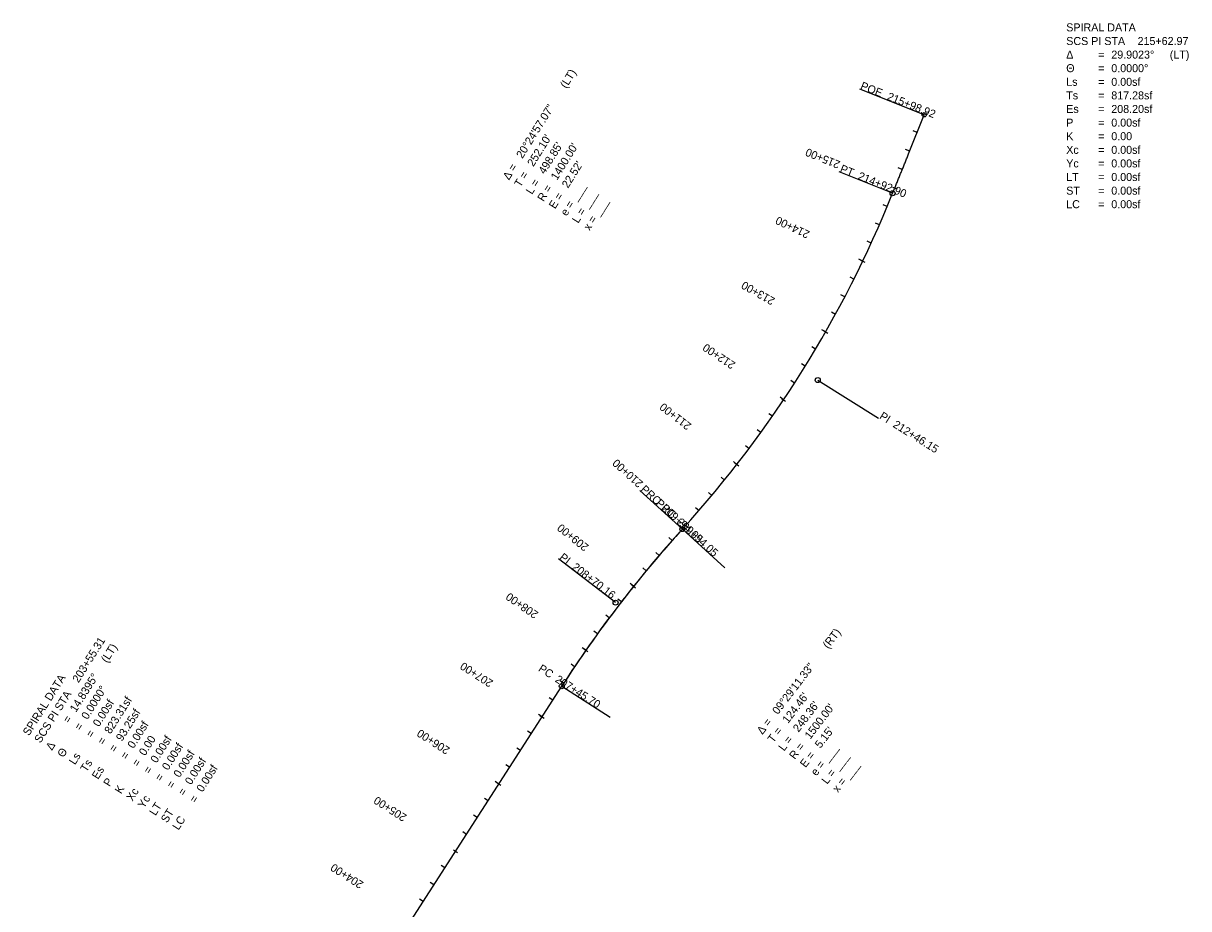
# Model space of a CAD drawing. Extents: x 14118619 to 14120230, y 8668091 to 8670317.
# Drawn here: x 14118771 to 14120230, y 8669208 to 8670317 of the extents above; entities that cross this region are included whole.
import ezdxf

# ---------------------------------------------------------------- set-up
doc = ezdxf.new("R2010")
doc.units = 0
for name, color, linetype in [('Default', 7, 'Continuous'), ('PhoBuilding', 7, 'Continuous'), ('PhoDrainageArrow', 7, 'Continuous'), ('PhoEdgeEntranceUnpaved', 7, 'Continuous'), ('PhoEdgeParkingUnpaved', 7, 'Continuous'), ('PhoGuardRail', 7, 'Continuous'), ('PhoRoadPoints', 7, 'Continuous')]:
    doc.layers.add(name, color=color, linetype=linetype)

msp = doc.modelspace()

# ---------------------------------------------------------------- linework, layer by layer
at = {"layer": 'Default'}
msp.add_open_spline([(14119859, 8670104.2), (14119859.4, 8670105), (14119860.1, 8670106.7), (14119861.1, 8670109.1), (14119862.1, 8670111.6), (14119863.1, 8670114), (14119864.1, 8670116.5), (14119865.1, 8670119), (14119866.1, 8670121.4), (14119867.1, 8670123.9), (14119868.1, 8670126.3), (14119869.1, 8670128.8), (14119870.1, 8670131.3), (14119871.1, 8670133.7), (14119872.1, 8670136.2), (14119873.1, 8670138.7), (14119874.1, 8670141.1), (14119875.1, 8670143.6), (14119876.1, 8670146.1), (14119877.1, 8670148.5), (14119878.1, 8670151), (14119878.7, 8670152.6), (14119879, 8670153.5)], degree=3, dxfattribs=at)
at = {"layer": 'PhoBuilding'}
for p, q in [((14119858.9, 8670111.9), (14119864.6, 8670109.6)), ((14119821.7, 8670019.2), (14119816.7, 8670021.5)), ((14119775.2, 8669930.6), (14119770.5, 8669933.3)), ((14119722.6, 8669845.6), (14119718.1, 8669848.7)), ((14119664, 8669764.6), (14119659.7, 8669768)), ((14119597.5, 8669690), (14119602.1, 8669685.9)), ((14119534.8, 8669612), (14119530.6, 8669615.4)), ((14119475, 8669531.9), (14119470.5, 8669535)), ((14119420.1, 8669448.3), (14119415.5, 8669451.3)), ((14119366, 8669364.2), (14119361.4, 8669367.2)), ((14119309.3, 8669281.8), (14119314.4, 8669278.5))]:
    msp.add_line(p, q, dxfattribs=at)
at = {"layer": 'PhoDrainageArrow'}
for p, q in [((14119889.8, 8670180.3), (14119884.7, 8670182.4)), ((14119880.5, 8670157.1), (14119875.4, 8670159.1)), ((14119871.2, 8670133.9), (14119866.1, 8670136)), ((14119858.9, 8670111.9), (14119864.6, 8670109.6)), ((14119852.3, 8670087.6), (14119847.2, 8670089.7)), ((14119842.5, 8670064.6), (14119837.5, 8670066.8)), ((14119832.3, 8670041.8), (14119827.3, 8670044.1)), ((14119818.9, 8670020.5), (14119824.4, 8670017.8)), ((14119810.7, 8669996.7), (14119805.8, 8669999.2)), ((14119799.2, 8669974.5), (14119794.4, 8669977)), ((14119787.4, 8669952.5), (14119782.6, 8669955.1)), ((14119772.6, 8669932.1), (14119777.9, 8669929.1)), ((14119762.6, 8669909), (14119758, 8669911.8)), ((14119749.7, 8669887.7), (14119745, 8669890.5)), ((14119736.3, 8669866.5), (14119731.7, 8669869.5)), ((14119720.1, 8669847.3), (14119725.1, 8669843.9)), ((14119708.5, 8669825), (14119704, 8669828.1)), ((14119694, 8669804.6), (14119689.6, 8669807.8)), ((14119679.2, 8669784.5), (14119674.8, 8669787.7)), ((14119661.6, 8669766.5), (14119666.4, 8669762.7)), ((14119648.5, 8669745), (14119644.2, 8669748.4)), ((14119632.6, 8669725.7), (14119628.4, 8669729.2)), ((14119616.4, 8669706.7), (14119612.3, 8669710.3)), ((14119597.5, 8669690), (14119602.1, 8669685.9)), ((14119583.1, 8669669.4), (14119579, 8669673)), ((14119566.7, 8669650.5), (14119562.5, 8669654.1)), ((14119550.6, 8669631.4), (14119546.4, 8669634.9)), ((14119532.4, 8669613.9), (14119537.2, 8669610.1)), ((14119519.4, 8669592.3), (14119515.1, 8669595.7)), ((14119504.3, 8669572.4), (14119499.9, 8669575.7)), ((14119489.5, 8669552.3), (14119485, 8669555.5)), ((14119472.5, 8669533.6), (14119477.5, 8669530.1)), ((14119460.9, 8669511.2), (14119456.4, 8669514.3)), ((14119447.1, 8669490.4), (14119442.6, 8669493.3)), ((14119433.6, 8669469.3), (14119429, 8669472.3)), ((14119417.5, 8669450), (14119422.7, 8669446.7)), ((14119406.6, 8669427.3), (14119402, 8669430.2)), ((14119393, 8669406.3), (14119388.4, 8669409.2)), ((14119379.5, 8669385.2), (14119374.9, 8669388.2)), ((14119363.4, 8669365.9), (14119368.6, 8669362.6)), ((14119352.5, 8669343.2), (14119347.9, 8669346.2)), ((14119338.9, 8669322.2), (14119334.3, 8669325.1)), ((14119325.4, 8669301.1), (14119320.8, 8669304.1)), ((14119309.3, 8669281.8), (14119314.4, 8669278.5)), ((14119298.3, 8669259.1), (14119293.8, 8669262.1)), ((14119284.8, 8669238.1), (14119280.2, 8669241)), ((14119271.3, 8669217.1), (14119266.7, 8669220))]:
    msp.add_line(p, q, dxfattribs=at)
at = {"layer": 'PhoEdgeEntranceUnpaved'}
msp.add_line((14119879, 8670153.5), (14119898.7, 8670202.6), dxfattribs=at)
for centre, radius, start, end in [((14118559.4, 8670624.8), 1400, 317.7561, 338.1719), ((14120706.3, 8668675.1), 1500, 137.7561, 147.2426)]:
    msp.add_arc(centre, radius, start, end, dxfattribs=at)
at = {"layer": 'PhoEdgeParkingUnpaved'}
for p, q in [((14119898.7, 8670202.6), (14119817.9, 8670234.8)), ((14119859, 8670104.2), (14119792.2, 8670131)), ((14119765.3, 8669870.2), (14119841.6, 8669822.4)), ((14119595.8, 8669683.6), (14119542.5, 8669732)), ((14119595.8, 8669683.6), (14119649.1, 8669635.1)), ((14119512.2, 8669591.4), (14119440.8, 8669646.2)), ((14119444.8, 8669486.7), (14119505.4, 8669447.8))]:
    msp.add_line(p, q, dxfattribs=at)
for centre, radius in [((14119898.7, 8670202.6), 2.67), ((14119859, 8670104.2), 3.12), ((14119765.3, 8669870.2), 3.12), ((14119595.8, 8669683.6), 3.12), ((14119595.8, 8669683.6), 3.12), ((14119512.2, 8669591.4), 3.12), ((14119444.8, 8669486.7), 3.12)]:
    msp.add_circle(centre, radius, dxfattribs=at)
at = {"layer": 'PhoGuardRail'}
for p, q in [((14119879, 8670153.5), (14119898.7, 8670202.6)), ((14119241.6, 8669170.9), (14119444.8, 8669486.7))]:
    msp.add_line(p, q, dxfattribs=at)
for centre, radius, start, end in [((14118559.4, 8670624.8), 1400, 317.7561, 338.1719), ((14120706.3, 8668675.1), 1500, 137.7561, 147.2426)]:
    msp.add_arc(centre, radius, start, end, dxfattribs=at)
msp.add_open_spline([(14119859, 8670104.2), (14119859.4, 8670105), (14119860.1, 8670106.7), (14119861.1, 8670109.1), (14119862.1, 8670111.6), (14119863.1, 8670114), (14119864.1, 8670116.5), (14119865.1, 8670119), (14119866.1, 8670121.4), (14119867.1, 8670123.9), (14119868.1, 8670126.3), (14119869.1, 8670128.8), (14119870.1, 8670131.3), (14119871.1, 8670133.7), (14119872.1, 8670136.2), (14119873.1, 8670138.7), (14119874.1, 8670141.1), (14119875.1, 8670143.6), (14119876.1, 8670146.1), (14119877.1, 8670148.5), (14119878.1, 8670151), (14119878.7, 8670152.6), (14119879, 8670153.5)], degree=3, dxfattribs=at)
at = {"layer": 'PhoRoadPoints'}
msp.add_line((14119241.6, 8669170.9), (14119444.8, 8669486.7), dxfattribs=at)
msp.add_arc((14120706.3, 8668675.1), 1500, 137.9326, 147.2426, dxfattribs=at)

# ---------------------------------------------------------------- texts
at = {"layer": 'PhoBuilding'}
for s, rotation, p in [('215+00', 157.6737, (14119794.3, 8670143.9)), ('210+00', 137.9995, (14119547.4, 8669741.9)), ('205+00', 147.2426, (14119251.5, 8669324.9))]:
    msp.add_text(s, height=10.02, rotation=rotation, dxfattribs=at).set_placement(p)
at = {"layer": 'PhoDrainageArrow'}
for s, rotation, p in [('215+00', 157.6737, (14119794.3, 8670143.9)), ('214+00', 154.3698, (14119756.2, 8670056.1)), ('213+00', 150.2772, (14119712.6, 8669972.2)), ('212+00', 146.1847, (14119663.1, 8669891.5)), ('211+00', 142.0921, (14119607.9, 8669814.6)), ('210+00', 137.9995, (14119547.4, 8669741.9)), ('209+00', 141.3486, (14119479.4, 8669662.7)), ('208+00', 145.1683, (14119416.3, 8669578.8)), ('207+00', 147.2426, (14119359.7, 8669493.1)), ('206+00', 147.2426, (14119305.6, 8669409)), ('205+00', 147.2426, (14119251.5, 8669324.9)), ('204+00', 147.2426, (14119197.4, 8669240.8))]:
    msp.add_text(s, height=10.02, rotation=rotation, dxfattribs=at).set_placement(p)
at = {"layer": 'PhoEdgeParkingUnpaved'}
for s, height, p in [('SPIRAL DATA', 10.02, (14120076.5, 8670307)), ('SCS PI STA ', 10.02, (14120076.5, 8670289.9)), ('215+62.97', 10.02, (14120165.8, 8670289.9)), ('Δ', 10, (14120076.5, 8670272.9)), ('= ', 10.02, (14120116.6, 8670272.9)), ('29.9023°', 10.02, (14120132.9, 8670272.9)), (' (LT)', 10.02, (14120202.4, 8670272.9)), ('Θ ', 10.02, (14120076.5, 8670255.9)), ('= ', 10.02, (14120116.6, 8670255.9)), ('0.0000°', 10.02, (14120132.9, 8670255.9)), ('Ls', 10.02, (14120076.5, 8670238.8)), ('= ', 10.02, (14120116.6, 8670238.8)), ('0.00sf', 10.02, (14120132.9, 8670238.8)), ('Ts', 10.02, (14120076.5, 8670221.8)), ('= ', 10.02, (14120116.6, 8670221.8)), ('817.28sf', 10.02, (14120132.9, 8670221.8)), ('Es', 10.02, (14120076.5, 8670204.8)), ('208.20sf', 10.02, (14120132.9, 8670204.8)), ('= ', 10.02, (14120116.6, 8670204.8)), ('0.00sf', 10.02, (14120132.9, 8670187.7)), ('P', 10, (14120076.5, 8670187.7)), ('= ', 10.02, (14120116.6, 8670187.7)), ('K', 10, (14120076.5, 8670170.7)), ('= ', 10.02, (14120116.6, 8670170.7)), ('0.00', 10.02, (14120132.9, 8670170.7)), ('Xc', 10.02, (14120076.5, 8670153.6)), ('= ', 10.02, (14120116.6, 8670153.6)), ('0.00sf', 10.02, (14120132.9, 8670153.6)), ('Yc', 10.02, (14120076.5, 8670136.6)), ('= ', 10.02, (14120116.6, 8670136.6)), ('0.00sf', 10.02, (14120132.9, 8670136.6)), ('LT', 10.02, (14120076.5, 8670119.6)), ('= ', 10.02, (14120116.6, 8670119.6)), ('0.00sf', 10.02, (14120132.9, 8670119.6)), ('ST ', 10.02, (14120076.5, 8670102.5)), ('0.00sf', 10.02, (14120132.9, 8670102.5)), ('= ', 10.02, (14120116.6, 8670102.5)), ('0.00sf', 10.02, (14120132.9, 8670085.5)), ('LC', 10.02, (14120076.5, 8670085.5)), ('= ', 10.02, (14120116.6, 8670085.5))]:
    msp.add_text(s, height=height, dxfattribs=at).set_placement(p)
for s, height, rotation, p in [(' (LT)', 10.02, 57.964, (14119448.5, 8670231.7)), ('POE ', 10.02, 338.2272, (14119817.9, 8670235)), ('215+98.92', 10.02, 338.2272, (14119851.3, 8670221.7)), ('20°24\'57.07"', 10.02, 57.964, (14119395.5, 8670147)), ("252.10'", 10.02, 57.964, (14119409.3, 8670136.9)), ("498.85'", 10.02, 57.964, (14119423.4, 8670127.3)), ("1400.00'", 10.02, 57.964, (14119438.8, 8670119.8)), ('Δ = ', 10.02, 57.964, (14119378.7, 8670120.1)), ("22.52'", 10.02, 57.964, (14119452.6, 8670109.8)), ('PT', 10.02, 338.1719, (14119792.3, 8670131.2)), ('T = ', 10.02, 57.964, (14119393.1, 8670111)), ('214+92.90', 10.02, 338.1719, (14119814.8, 8670122.1)), ('L = ', 10.02, 57.964, (14119407.5, 8670102)), ('R = ', 10.02, 57.964, (14119422, 8670093)), ('e = ___ ', 10.02, 57.964, (14119450.9, 8670074.9)), ('E = ', 10.02, 57.964, (14119436.4, 8670083.9)), ('L = ___', 10.02, 57.964, (14119465.3, 8670065.9)), ('x = ___', 10.02, 57.964, (14119479.7, 8670056.8)), ('PI ', 10.02, 327.964, (14119841.7, 8669822.6)), ('212+46.15', 10.02, 327.964, (14119858.6, 8669812)), ('PRC', 10.02, 317.7561, (14119542.7, 8669732.1)), ('PRC', 10.02, 317.7561, (14119561.7, 8669714.8)), ('209+94.05', 10.02, 317.7561, (14119569, 8669708.2)), ('209+94.05', 10.02, 317.7561, (14119588, 8669690.9)), ('PI ', 10.02, 322.4993, (14119440.9, 8669646.4)), ('208+70.16', 10.02, 322.4993, (14119456.7, 8669634.2)), (' (RT)', 10.02, 52.4993, (14119776.3, 8669530)), ('203+55.31', 10.02, 57.7513, (14118839.7, 8669490.3)), (' (LT)', 10.02, 57.7513, (14118873.6, 8669512.1)), ('PC', 10.02, 327.2426, (14119414.6, 8669506.4)), ('09°29\'11.33"', 10.02, 52.4993, (14119715.4, 8669450.6)), ('SPIRAL DATA', 10.02, 57.7513, (14118777.6, 8669423.8)), ('14.8395°', 10.02, 57.7513, (14118836.5, 8669453.3)), ('207+45.70', 10.02, 327.2426, (14119435.6, 8669492.9)), ('0.0000°', 10.02, 57.7513, (14118850.9, 8669444.2)), ('SCS PI STA ', 10.02, 57.7513, (14118792, 8669414.7)), ('0.00sf', 10.02, 57.7513, (14118865.3, 8669435.1)), ('823.31sf', 10.02, 57.7513, (14118879.7, 8669426.1)), ("124.46'", 10.02, 52.4993, (14119728.1, 8669439.3)), ("248.36'", 10.02, 52.4993, (14119741.3, 8669428.4)), ('93.25sf', 10.02, 57.7513, (14118894.2, 8669417)), ("1500.00'", 10.02, 52.4993, (14119755.9, 8669419.5)), ('= ', 10.02, 57.7513, (14118827.8, 8669439.5)), ('= ', 10.02, 57.7513, (14118842.2, 8669430.4)), ('0.00sf', 10.02, 57.7513, (14118908.6, 8669407.9)), ('Δ = ', 10.02, 52.4993, (14119696.1, 8669425.5)), ('= ', 10.02, 57.7513, (14118856.6, 8669421.4)), ('0.00', 10.02, 57.7513, (14118923, 8669398.8)), ('0.00sf', 10.02, 57.7513, (14118937.4, 8669389.7)), ('T = ', 10.02, 52.4993, (14119709.6, 8669415.1)), ("5.15'", 10.02, 52.4993, (14119768.7, 8669408.2)), ('Δ', 10, 57.7513, (14118806.4, 8669405.6)), ('= ', 10.02, 57.7513, (14118871, 8669412.3)), ('= ', 10.02, 57.7513, (14118885.5, 8669403.2)), ('0.00sf', 10.02, 57.7513, (14118951.8, 8669380.6)), ('L = ', 10.02, 52.4993, (14119723.1, 8669404.7)), ('R = ', 10.02, 52.4993, (14119736.6, 8669394.3)), ('Θ ', 10.02, 57.7513, (14118820.8, 8669396.6)), ('Ls', 10.02, 57.7513, (14118835.3, 8669387.5)), ('= ', 10.02, 57.7513, (14118899.9, 8669394.1)), ('0.00sf', 10.02, 57.7513, (14118966.2, 8669371.5)), ('0.00sf', 10.02, 57.7513, (14118980.6, 8669362.4)), ('E = ', 10.02, 52.4993, (14119750.1, 8669384)), ('e = ___ ', 10.02, 52.4993, (14119763.6, 8669373.6)), ('L = ___', 10.02, 52.4993, (14119777.1, 8669363.2)), ('Ts', 10.02, 57.7513, (14118849.7, 8669378.4)), ('Es', 10.02, 57.7513, (14118864.1, 8669369.3)), ('= ', 10.02, 57.7513, (14118914.3, 8669385)), ('= ', 10.02, 57.7513, (14118928.7, 8669375.9)), ('0.00sf', 10.02, 57.7513, (14118995, 8669353.3)), ('x = ___', 10.02, 52.4993, (14119790.7, 8669352.9)), ('P', 10, 57.7513, (14118878.5, 8669360.2)), ('= ', 10.02, 57.7513, (14118943.1, 8669366.8)), ('= ', 10.02, 57.7513, (14118957.5, 8669357.7)), ('K', 10, 57.7513, (14118892.9, 8669351.1)), ('Xc', 10.02, 57.7513, (14118907.3, 8669342)), ('= ', 10.02, 57.7513, (14118971.9, 8669348.6)), ('Yc', 10.02, 57.7513, (14118921.7, 8669332.9)), ('LT', 10.02, 57.7513, (14118936.1, 8669323.8)), ('= ', 10.02, 57.7513, (14118986.3, 8669339.6)), ('ST ', 10.02, 57.7513, (14118950.5, 8669314.7)), ('LC', 10.02, 57.7513, (14118964.9, 8669305.7))]:
    msp.add_text(s, height=height, rotation=rotation, dxfattribs=at).set_placement(p)

doc.saveas('drawing.dxf')
